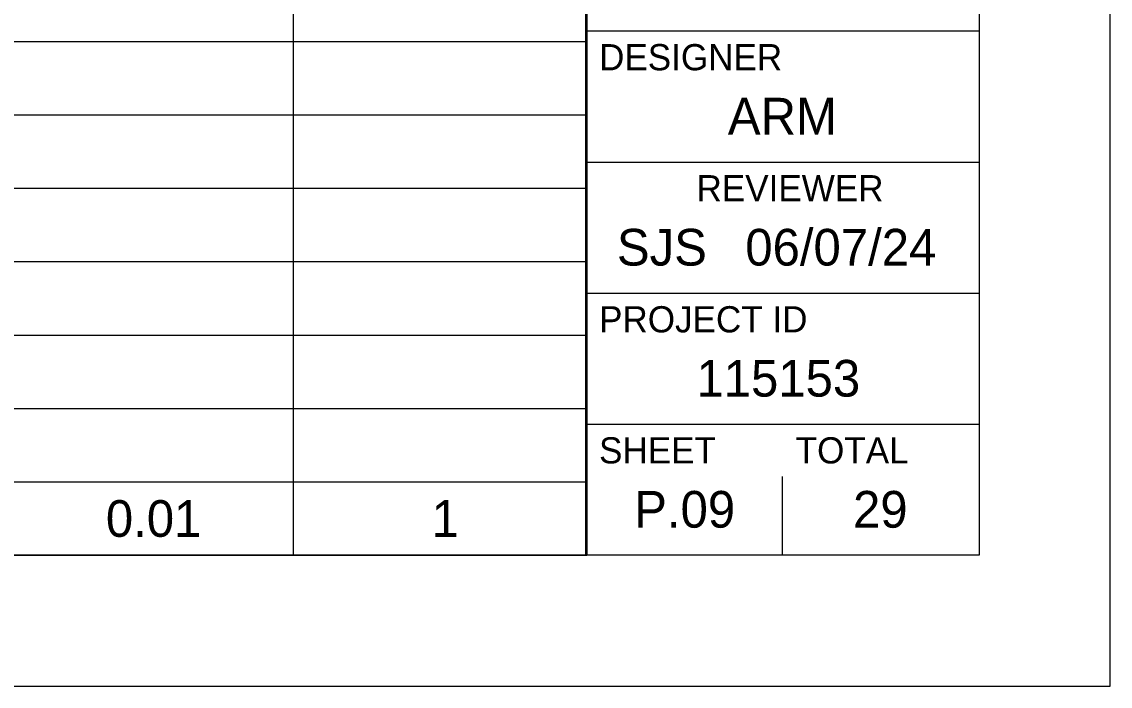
# Model space of a CAD drawing. Extents: x 0 to 34, y 0 to 22.
# Drawn here: x 29.848 to 34, y 0 to 2.535 of the extents above; entities that cross this region are included whole.
import ezdxf

# ---------------------------------------------------------------- set-up
doc = ezdxf.new("R2010")
doc.units = 0
for name, color, linetype in [('SH_Border', 7, 'Continuous'), ('SH_Cut_Line', 7, 'Continuous'), ('SH_Data', 7, 'Continuous'), ('SH_Text', 7, 'Continuous')]:
    doc.layers.add(name, color=color, linetype=linetype)

msp = doc.modelspace()

# ---------------------------------------------------------------- linework, layer by layer
at = {"layer": 'SH_Border'}
for p, q in [((32, 0.5), (32, 21.5)), ((32, 2.5), (33.5, 2.5)), ((32, 2), (33.5, 2)), ((32, 1.5), (33.5, 1.5)), ((32, 1), (33.5, 1))]:
    msp.add_line(p, q, dxfattribs=at)
msp.add_lwpolyline([(1.5, 21.5), (33.5, 21.5), (33.5, 0.5), (1.5, 0.5)], close=True, dxfattribs=at)
at = {"layer": 'SH_Cut_Line'}
msp.add_lwpolyline([(0, 0), (34, 0), (34, 22), (0, 22)], close=True, dxfattribs=at)
at = {"layer": 'SH_Data'}
for p, q in [((32.75, 0.5), (32.75, 0.8)), ((32.375, 0.675), (32.375, 0.675))]:
    msp.add_line(p, q, dxfattribs=at)
at = {"layer": 'SH_Text'}
for p, q in [((30.8836, 21.5), (30.8836, 0.5)), ((32.0036, 21.5), (32.0036, 0.5)), ((1.5, 2.46), (32.0036, 2.46)), ((1.5, 2.18), (32.0036, 2.18)), ((1.5, 1.9), (32.0036, 1.9)), ((1.5, 1.62), (32.0036, 1.62)), ((1.5, 1.34), (32.0036, 1.34)), ((1.5, 1.06), (32.0036, 1.06)), ((1.5, 0.78), (32.0036, 0.78)), ((1.5, 0.5), (32.0036, 0.5))]:
    msp.add_line(p, q, dxfattribs=at)

# ---------------------------------------------------------------- texts
at = {"layer": 'SH_Data'}
for s, height, p in [('DESIGNER', 0.1, (32.05, 2.35)), ('ARM', 0.14, (32.5412, 2.105)), ('REVIEWER', 0.1, (32.4218, 1.85)), ('SJS', 0.14, (32.118, 1.605)), ('06/07/24', 0.14, (32.6078, 1.605)), ('PROJECT ID', 0.1, (32.05, 1.35)), ('115153', 0.14, (32.4215, 1.105)), ('SHEET', 0.1, (32.05, 0.85)), ('TOTAL', 0.1, (32.8, 0.85)), ('P.09', 0.14, (32.184, 0.605)), ('29', 0.14, (33.0188, 0.605))]:
    msp.add_text(s, height=height, dxfattribs=at).set_placement(p)
at = {"layer": 'SH_Text'}
for s, p in [('0.01', (30.1685, 0.57)), ('1', (31.4108, 0.57))]:
    msp.add_text(s, height=0.14, dxfattribs=at).set_placement(p)

doc.saveas('drawing.dxf')
